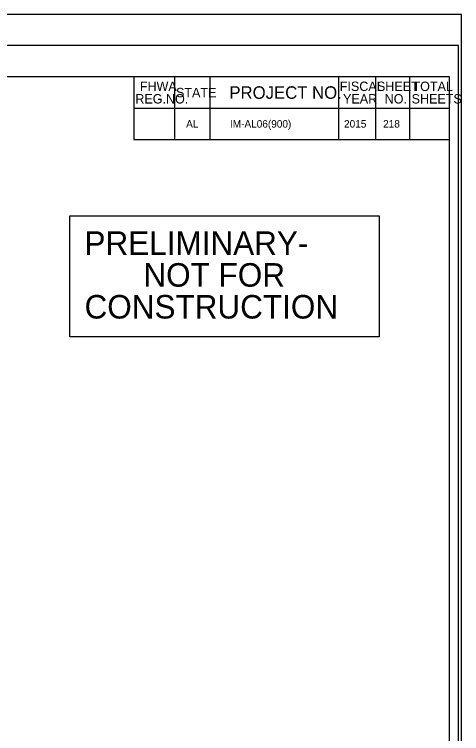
# Model space of a CAD drawing. Extents: x 504255 to 505955, y 659986 to 661086.
# Drawn here: x 505613 to 505955, y 660536 to 661086 of the extents above; entities that cross this region are included whole.
import ezdxf

# ---------------------------------------------------------------- set-up
doc = ezdxf.new("R2010")
doc.units = 0
for name, color, linetype in [('1', 7, 'Continuous'), ('Level 62', 7, 'Continuous'), ('Level1', 7, 'Continuous'), ('Level5', 7, 'Continuous')]:
    doc.layers.add(name, color=color, linetype=linetype)

msp = doc.modelspace()

# ---------------------------------------------------------------- linework, layer by layer
at = {"layer": '1'}
msp.add_lwpolyline([(505655.9, 660932.39), (505892.32, 660932.39), (505892.32, 660839.75), (505655.9, 660839.75)], close=True, dxfattribs=at)
at = {"layer": 'Level 62'}
msp.add_lwpolyline([(505955.48, 661086.39), (504255.48, 661086.39), (504255.48, 659986.39), (505955.48, 659986.39)], close=True, dxfattribs=at)
at = {"layer": 'Level1'}
for p, q in [((505735.94, 661038.56), (505735.94, 660990.73)), ((505762.85, 661038.58), (505762.85, 660990.75)), ((505861.26, 661038.56), (505861.26, 660990.74)), ((505889.53, 661038.57), (505889.53, 660990.74)), ((505915.54, 661038.57), (505915.54, 660990.75)), ((505946.29, 661038.56), (505946.29, 661038.56)), ((505946.29, 661033.78), (505946.29, 661033.78)), ((505704.76, 661014.65), (505946.29, 661014.65))]:
    msp.add_line(p, q, dxfattribs=at)
for points in [[(504257.9, 660010.3), (505953.07, 660010.3), (505953.07, 661062.47), (504257.9, 661062.47), (504257.9, 660010.3)], [(504327.92, 660023.67), (505946.29, 660023.67), (505946.29, 661038.56), (504327.92, 661038.56), (504327.92, 660023.67)], [(505704.76, 660990.74), (505946.29, 660990.74), (505946.29, 661038.56), (505704.76, 661038.56), (505704.76, 660990.74)]]:
    msp.add_lwpolyline(points, dxfattribs=at)

# ---------------------------------------------------------------- texts
at = {"layer": '1'}
for s, p in [('PRELIMINARY-', (505667.08, 660902.51)), ('NOT FOR', (505712.12, 660878.16)), ('CONSTRUCTION', (505667.12, 660853.8))]:
    msp.add_text(s, height=18, dxfattribs=at).set_placement(p)
at = {"layer": 'Level1'}
for s, height, p in [('FHWA', 7.174, (505709.39, 661027.81)), ('FISCAL', 7.174, (505862.3, 661027.81)), ('SHEET', 7.174, (505890.72, 661027.81)), ('TOTAL', 7.174, (505917.91, 661027.81)), ('STATE', 7.174, (505737.07, 661023.02)), ('PROJECT NO.', 9.5652, (505777.9, 661021.83)), ('REG.NO.', 7.174, (505705.96, 661018.24)), ('YEAR', 7.174, (505864.81, 661018.24)), ('NO.', 7.174, (505896.63, 661018.24)), ('SHEETS', 7.174, (505917.25, 661018.24))]:
    msp.add_text(s, height=height, dxfattribs=at).set_placement(p)
at = {"layer": 'Level5'}
for s, height, p in [('AL', 5.739, (505744.82, 660999.83)), ('IM-AL06(900)', 5.7391, (505778.33, 660999.79)), ('2015', 5.739, (505865.57, 660999.83)), ('218', 5.739, (505895.45, 660999.83))]:
    msp.add_text(s, height=height, dxfattribs=at).set_placement(p)

doc.saveas('drawing.dxf')
